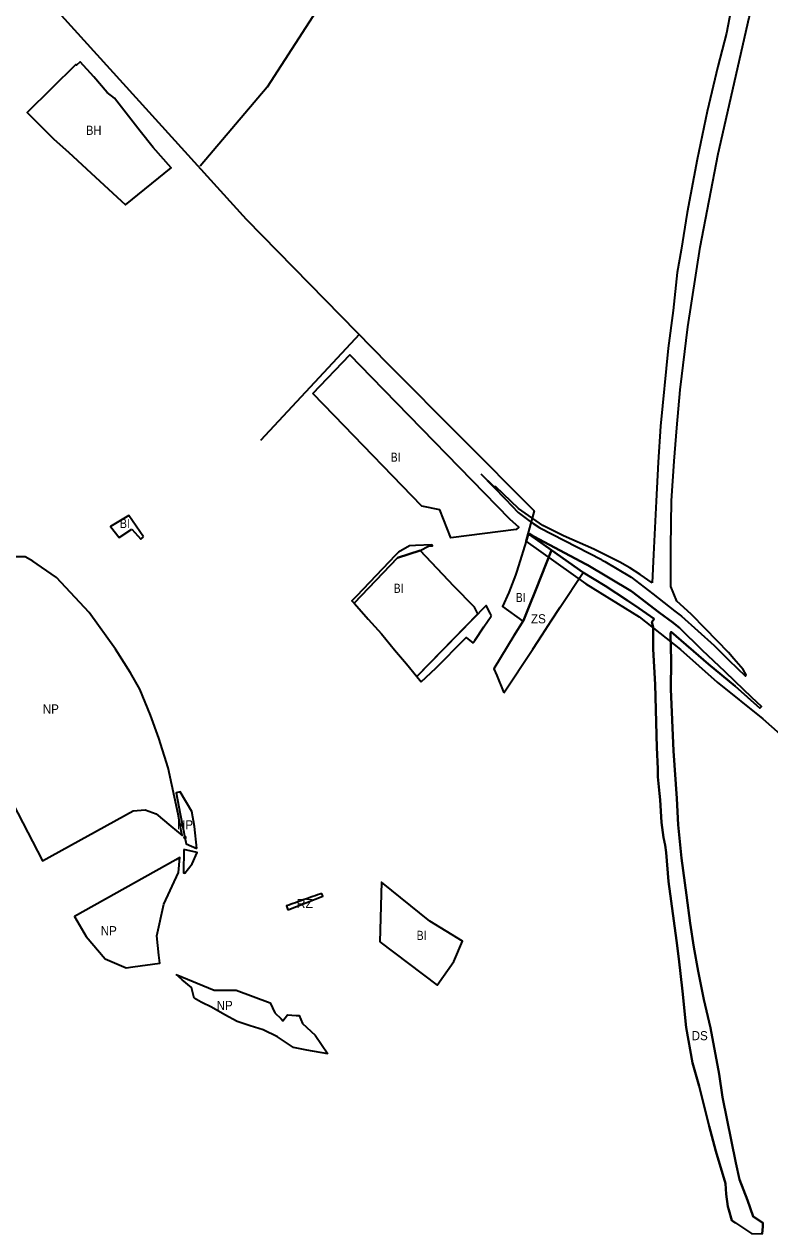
# Model space of a CAD drawing. Extents: x -650276 to -642489, y -1074311 to -1066658.
# Drawn here: x -646196 to -645218, y -1073293 to -1071706 of the extents above; entities that cross this region are included whole.
import ezdxf

# ---------------------------------------------------------------- set-up
doc = ezdxf.new("R2010")
doc.units = 0
doc.header["$LTSCALE"] = 4.8
doc.header["$PDMODE"] = 32
doc.header["$PDSIZE"] = 2.4
for name, color, linetype, lineweight in [('1', 7, 'Continuous', 35), ('15', 7, 'Continuous', 35), ('2', 7, 'Continuous', 35), ('24', 7, 'Continuous', 35), ('41', 7, 'Continuous', 35), ('48', 7, 'Continuous', 35), ('54', 7, 'Continuous', 35), ('6', 7, 'Continuous', 35)]:
    doc.layers.add(name, color=color, linetype=linetype, lineweight=lineweight)
doc.layers.add('62', color=7, linetype='Continuous')
doc.layers.add('63', color=7, linetype='Continuous')

msp = doc.modelspace()

# ---------------------------------------------------------------- linework, layer by layer
at = {"layer": '1'}
msp.add_lwpolyline([(-646102.04, -1071906.4), (-646068.317, -1071937.555), (-646062.91, -1071942.55), (-646002.93, -1071893.984), (-646026.64, -1071867.44), (-646043.49, -1071845.87), (-646077.32, -1071802.59), (-646087, -1071795), (-646104.5, -1071774.86), (-646122.16, -1071754.78), (-646127.12, -1071759.15), (-646127.84, -1071758.53), (-646191.57, -1071821.44), (-646174.69, -1071838.69), (-646156.59, -1071856.53), (-646137.74, -1071873.31)], close=True, dxfattribs=at)
at = {"layer": '15'}
for points in [[(-645763.06, -1072465.26), (-645706.039, -1072405.769), (-645676.53, -1072396.16)], [(-645661.3, -1072388.74), (-645682.59, -1072389.76), (-645690.37, -1072390.13), (-645705, -1072398.19), (-645708.94, -1072402.11)], [(-645676.53, -1072396.16), (-645676.53, -1072396.16), (-645665.32, -1072390.32), (-645660.16, -1072389.95), (-645661.3, -1072388.74)], [(-645708.94, -1072402.11), (-645760.02, -1072455.94), (-645765.95, -1072462.03), (-645763.06, -1072465.26)], [(-645582.84, -1072481.71), (-645584.46, -1072478.58), (-645589.862, -1072468.109), (-645680.87, -1072561.42), (-645675.13, -1072568.36)], [(-645607.07, -1072517.61), (-645605.95, -1072515.95), (-645604.82, -1072514.3), (-645592.9, -1072496.52), (-645583.13, -1072482.13), (-645582.84, -1072481.71)], [(-645675.13, -1072568.36), (-645655.65, -1072550.62), (-645617.87, -1072512.12), (-645615.95, -1072510.16), (-645607.07, -1072517.61)]]:
    msp.add_lwpolyline(points, dxfattribs=at)
at = {"layer": '2'}
msp.add_line((-645553.35, -1072508.1), (-645541.09, -1072487.98), dxfattribs=at)
for points in [[(-645817.219, -1072189.975), (-645768.649, -1072139.283), (-645740.45, -1072168.23), (-645559.34, -1072354.42), (-645546.82, -1072365.72), (-645550.41, -1072368.47), (-645636.37, -1072379.57), (-645650.78, -1072342.73), (-645674, -1072338), (-645789.298, -1072218.833)], [(-645729.36, -1072909.65), (-645654.16, -1072966.3), (-645632.23, -1072935.28), (-645620.92, -1072908.65), (-645663.52, -1072882.58), (-645726.9, -1072831.5)]]:
    msp.add_lwpolyline(points, close=True, dxfattribs=at)
for points in [[(-646039.16, -1072378.43), (-646058.64, -1072350.29), (-646082.55, -1072364.84), (-646071, -1072379.27), (-646054.43, -1072368.34)], [(-646054.43, -1072368.34), (-646042.65, -1072381.23), (-646039.16, -1072378.43)], [(-645541.09, -1072487.98), (-645533.15, -1072468.21), (-645524.87, -1072447.61), (-645503.98, -1072395.64), (-645532.75, -1072375.41), (-645535.05, -1072376.72), (-645549.6, -1072423.39), (-645551.54, -1072428.66), (-645559.92, -1072451.41), (-645568.38, -1072469.68), (-645541.56, -1072488.74)], [(-645632.1, -1072442.93), (-645676.53, -1072396.16), (-645706.039, -1072405.769), (-645763.06, -1072465.26), (-645753.128, -1072476.383), (-645744.38, -1072486.18), (-645726.95, -1072505.7), (-645709.92, -1072526.3), (-645694.51, -1072544.93), (-645680.87, -1072561.42), (-645600.883, -1072479.409)], [(-645632.1, -1072442.93), (-645638.82, -1072435.99), (-645676.53, -1072396.16), (-645706.039, -1072405.769), (-645763.06, -1072465.26), (-645753.128, -1072476.383)], [(-645600.945, -1072479.473), (-645605.17, -1072470.52), (-645632.1, -1072442.93)], [(-645753.128, -1072476.383), (-645744.38, -1072486.18), (-645726.95, -1072505.7), (-645709.92, -1072526.3)], [(-645709.92, -1072526.3), (-645694.51, -1072544.93), (-645680.87, -1072561.42), (-645600.945, -1072479.473)]]:
    msp.add_lwpolyline(points, dxfattribs=at)
at = {"layer": '24'}
msp.add_line((-645267.525, -1073275.443), (-645271.518, -1073261.16), dxfattribs=at)
for points in [[(-645339.904, -1072462.677), (-645347.551, -1072443.527), (-645347.677, -1072391.355), (-645346.62, -1072330.914), (-645343.458, -1072278.998), (-645339.908, -1072235.158), (-645335.367, -1072185.207), (-645325.498, -1072102.789), (-645309.01, -1071998.147), (-645285.617, -1071875.733), (-645244.798, -1071696.585), (-645235.793, -1071663.703), (-645230.436, -1071634.261), (-645227.905, -1071625.277), (-645222.48, -1071606.08)], [(-645339.904, -1072462.677), (-645347.551, -1072443.527), (-645347.677, -1072391.355), (-645346.62, -1072330.914), (-645343.458, -1072278.998), (-645339.908, -1072235.158), (-645335.367, -1072185.207), (-645325.498, -1072102.789), (-645309.01, -1071998.147), (-645285.617, -1071875.733), (-645244.798, -1071696.585), (-645235.793, -1071663.703), (-645230.436, -1071634.261), (-645227.905, -1071625.277), (-645222.48, -1071606.08)], [(-645255.662, -1071626.67), (-645261.094, -1071645.025), (-645264.841, -1071657.687), (-645269.077, -1071687.396), (-645274.868, -1071717.176), (-645286.175, -1071761.228), (-645300.076, -1071820.179), (-645313.153, -1071883.081), (-645326.343, -1071952.807)], [(-645255.662, -1071626.67), (-645261.094, -1071645.025), (-645264.841, -1071657.687), (-645269.077, -1071687.396), (-645274.868, -1071717.176), (-645286.175, -1071761.228), (-645300.076, -1071820.179), (-645313.153, -1071883.081)], [(-645313.153, -1071883.081), (-645326.343, -1071952.807), (-645334.118, -1072001.954), (-645339.455, -1072031.565), (-645344.819, -1072081.225), (-645351.358, -1072130.815), (-645361.317, -1072232.824), (-645364.435, -1072280.268), (-645366.951, -1072331.609), (-645370.624, -1072401.447), (-645372.228, -1072438.764)], [(-645326.343, -1071952.807), (-645334.118, -1072001.954), (-645339.455, -1072031.565), (-645344.819, -1072081.225), (-645351.358, -1072130.815), (-645361.317, -1072232.824), (-645364.435, -1072280.268), (-645366.951, -1072331.609), (-645370.624, -1072401.447), (-645372.228, -1072438.764)], [(-645372.228, -1072438.764), (-645387.894, -1072427.453), (-645401.441, -1072419.033), (-645414.631, -1072411.611), (-645448.831, -1072394.325), (-645488.64, -1072376.782), (-645515.437, -1072363.447), (-645547.593, -1072340.827), (-645577.33, -1072312.704), (-645579.217, -1072312.425), (-645596.405, -1072296.114)], [(-645596.405, -1072296.114), (-645564.4, -1072328.61), (-645547.72, -1072346.19), (-645532.07, -1072358.01), (-645531.65, -1072358.29), (-645528.27, -1072360.53), (-645519.57, -1072366.3), (-645438.64, -1072408.1)], [(-645372.228, -1072438.764), (-645387.894, -1072427.453), (-645401.441, -1072419.033), (-645414.631, -1072411.611), (-645448.831, -1072394.325), (-645488.64, -1072376.782), (-645515.437, -1072363.447), (-645547.593, -1072340.827), (-645577.33, -1072312.704), (-645579.217, -1072312.425), (-645596.405, -1072296.114)], [(-645596.405, -1072296.114), (-645564.4, -1072328.61), (-645547.72, -1072346.19), (-645532.07, -1072358.01), (-645531.65, -1072358.29), (-645528.27, -1072360.53), (-645519.57, -1072366.3), (-645438.64, -1072408.1)], [(-645462.646, -1072425.015), (-645503.98, -1072395.64), (-645532.75, -1072375.41), (-645534.3, -1072374.33), (-645533.08, -1072373.71)], [(-645533.08, -1072373.71), (-645534.3, -1072374.33), (-645532.75, -1072375.41), (-645503.98, -1072395.64), (-645462.65, -1072425.01)], [(-645533.08, -1072373.71), (-645527.33, -1072377.73), (-645459.31, -1072413.95), (-645456.52, -1072415.6), (-645400.12, -1072449.03), (-645396.94, -1072451.44), (-645370.226, -1072471.736)], [(-645456.52, -1072415.6), (-645459.31, -1072413.95), (-645527.33, -1072377.73), (-645533.08, -1072373.71)], [(-645438.64, -1072408.1), (-645437.6, -1072408.64), (-645434.19, -1072410.67), (-645399.77, -1072431.12), (-645371.356, -1072453.119), (-645342.284, -1072475.625)], [(-645438.64, -1072408.1), (-645437.6, -1072408.64), (-645434.19, -1072410.67), (-645399.77, -1072431.12), (-645371.356, -1072453.119), (-645342.284, -1072475.625), (-645333.62, -1072482.33), (-645290.76, -1072520.92)], [(-645369.364, -1072485.931), (-645389.731, -1072471.612), (-645404.64, -1072461.72), (-645433.91, -1072442.56), (-645462.646, -1072425.015)], [(-645462.646, -1072425.015), (-645433.91, -1072442.56), (-645404.64, -1072461.72), (-645389.731, -1072471.612), (-645369.364, -1072485.931)], [(-645396.94, -1072451.44), (-645400.12, -1072449.03), (-645456.52, -1072415.6)], [(-645345.079, -1072490.836), (-645362.81, -1072477.37), (-645370.226, -1072471.736), (-645396.94, -1072451.44)], [(-645370.226, -1072471.736), (-645362.81, -1072477.37), (-645345.079, -1072490.836)], [(-645342.284, -1072475.625), (-645333.62, -1072482.33), (-645290.76, -1072520.92)], [(-645290.76, -1072520.92), (-645271.74, -1072539.96), (-645249.9, -1072561.25), (-645248.967, -1072559.511), (-645252.768, -1072552.178), (-645265.009, -1072538.358), (-645272.276, -1072530.154), (-645302.303, -1072499.014), (-645320.805, -1072479.495), (-645339.904, -1072462.677)], [(-645290.76, -1072520.92), (-645271.74, -1072539.96), (-645249.9, -1072561.25), (-645248.967, -1072559.511), (-645252.768, -1072552.178), (-645265.009, -1072538.358), (-645272.276, -1072530.154), (-645302.303, -1072499.014), (-645320.805, -1072479.495), (-645339.904, -1072462.677)], [(-645364.524, -1072682.575), (-645366.022, -1072654.462), (-645368.173, -1072571.881), (-645370.755, -1072525.734), (-645370.928, -1072496.619), (-645372.72, -1072490.314), (-645369.364, -1072485.931)], [(-645369.364, -1072485.931), (-645372.72, -1072490.314), (-645370.928, -1072496.619), (-645370.755, -1072525.734)], [(-645345.079, -1072490.836), (-645336.33, -1072497.48), (-645306.46, -1072527.08), (-645276.93, -1072555.11), (-645263.7, -1072567.8), (-645242, -1072588.6), (-645241.87, -1072588.722), (-645228.96, -1072600.865), (-645230.845, -1072602.888)], [(-645242, -1072588.6), (-645263.7, -1072567.8), (-645276.93, -1072555.11), (-645306.46, -1072527.08), (-645336.33, -1072497.48), (-645345.079, -1072490.836)], [(-645347.292, -1072502.877), (-645348.253, -1072505.583), (-645347.214, -1072540.97), (-645347.795, -1072577.893), (-645344.152, -1072658.857), (-645339.96, -1072721.587), (-645338.023, -1072755.969), (-645333.718, -1072799.987)], [(-645338.023, -1072755.969), (-645339.96, -1072721.587), (-645344.152, -1072658.857), (-645347.795, -1072577.893), (-645347.214, -1072540.97), (-645348.253, -1072505.583), (-645347.292, -1072502.877), (-645298.498, -1072545.352)], [(-645230.845, -1072602.888), (-645263.217, -1072574.314), (-645298.498, -1072545.352), (-645347.292, -1072502.877)], [(-645370.755, -1072525.734), (-645368.173, -1072571.881), (-645366.022, -1072654.462), (-645364.524, -1072682.575), (-645364.786, -1072692.977), (-645362.708, -1072714.781)], [(-645298.498, -1072545.352), (-645263.217, -1072574.314), (-645230.845, -1072602.888), (-645228.96, -1072600.865), (-645241.87, -1072588.722), (-645242, -1072588.6)], [(-645357.272, -1072772.771), (-645359.76, -1072752.865), (-645361.874, -1072723.527), (-645362.708, -1072714.781), (-645364.786, -1072692.977), (-645364.524, -1072682.575)], [(-645362.708, -1072714.781), (-645361.874, -1072723.527), (-645359.76, -1072752.865), (-645357.272, -1072772.771), (-645355.121, -1072782.993)], [(-645317.65, -1072916.642), (-645322.284, -1072885.085), (-645327.091, -1072848.387), (-645333.718, -1072799.987), (-645338.023, -1072755.969)], [(-645271.518, -1073261.16), (-645272.747, -1073256.762), (-645275.269, -1073240.71), (-645276.125, -1073226.571), (-645288.647, -1073184.518), (-645297.395, -1073151.294), (-645310.558, -1073098.946), (-645319.052, -1073068.6), (-645327.554, -1073022.214), (-645332.517, -1072974.538), (-645337.34, -1072932.073), (-645340.345, -1072908.029), (-645350.822, -1072830.388), (-645354.019, -1072792.454), (-645355.121, -1072782.993), (-645357.272, -1072772.771)], [(-645355.121, -1072782.993), (-645354.019, -1072792.454), (-645350.822, -1072830.388), (-645340.345, -1072908.029), (-645337.34, -1072932.073), (-645332.517, -1072974.538), (-645327.554, -1073022.214), (-645319.052, -1073068.6), (-645310.558, -1073098.946), (-645297.395, -1073151.294), (-645288.647, -1073184.518), (-645276.125, -1073226.571), (-645275.269, -1073240.71), (-645272.747, -1073256.762), (-645271.518, -1073261.16), (-645267.525, -1073275.443), (-645263.03, -1073278.25), (-645241.72, -1073292.2), (-645227.744, -1073292.736), (-645227.199, -1073283.366), (-645226.847, -1073278.345), (-645239.9, -1073270.025), (-645247.051, -1073248.736), (-645257.842, -1073221.36)], [(-645333.718, -1072799.987), (-645327.091, -1072848.387), (-645322.284, -1072885.085), (-645317.65, -1072916.642)], [(-645317.65, -1072916.642), (-645311.772, -1072947.945), (-645304.24, -1072985.372), (-645295.788, -1073022.556)], [(-645304.24, -1072985.372), (-645311.772, -1072947.945), (-645317.65, -1072916.642)], [(-645257.842, -1073221.36), (-645262.388, -1073199.409), (-645279.878, -1073113.356), (-645284.269, -1073083.286), (-645295.788, -1073022.556), (-645304.24, -1072985.372)], [(-645295.788, -1073022.556), (-645284.269, -1073083.286), (-645279.878, -1073113.356), (-645262.388, -1073199.409), (-645257.842, -1073221.36), (-645247.051, -1073248.736), (-645239.9, -1073270.025), (-645226.847, -1073278.345), (-645227.199, -1073283.366), (-645227.744, -1073292.736)]]:
    msp.add_lwpolyline(points, dxfattribs=at)
at = {"layer": '41'}
msp.add_line((-645566.54, -1072582.88), (-645528.81, -1072525.54), dxfattribs=at)
msp.add_lwpolyline([(-645528.81, -1072525.54), (-645516.37, -1072506.64), (-645504.48, -1072488.58), (-645492.61, -1072470.54), (-645462.65, -1072425.01), (-645503.98, -1072395.64), (-645524.87, -1072447.61), (-645533.15, -1072468.21), (-645541.09, -1072487.98), (-645553.35, -1072508.1), (-645579.76, -1072551.45), (-645575.9, -1072560.13), (-645566.54, -1072582.88)], dxfattribs=at)
at = {"layer": '48'}
for points in [[(-646236.97, -1072678.31), (-646171.72, -1072803.51), (-646052.58, -1072737.82), (-646037.23, -1072736.38), (-646022.4, -1072741.58), (-646003.22, -1072757.85), (-645988.43, -1072769.93), (-645990.04, -1072761.78), (-645993.89, -1072742.23), (-646006.66, -1072681.4), (-646019.16, -1072642.35), (-646030.17, -1072612.31), (-646043.87, -1072578.12), (-646056.42, -1072556.49), (-646075.82, -1072525.54), (-646110.61, -1072477.49), (-646153.49, -1072431.54), (-646172.81, -1072418.2), (-646184.449, -1072410.256), (-646194.19, -1072404.62), (-646254.75, -1072404.25)], [(-645969.46, -1072787.03), (-645972.31, -1072758.48), (-645975.86, -1072738.61), (-645991.31, -1072712.86), (-645996.31, -1072714.11), (-645990.95, -1072741.65), (-645987.1, -1072761.2), (-645984.79, -1072772.91)], [(-645984.79, -1072772.91), (-645983.22, -1072780.88), (-645969.46, -1072787.03)], [(-645986.24, -1072788.33), (-645986.71, -1072819.26), (-645986.71, -1072819.26)], [(-645975.3, -1072807.37), (-645969.01, -1072792.28), (-645986.24, -1072788.33)], [(-645986.71, -1072819.26), (-645986.71, -1072819.26), (-645985.19, -1072819.72), (-645975.3, -1072807.37)], [(-645972.6, -1072983.41), (-645976.48, -1072969.55), (-645988.49, -1072959.28), (-645996.2, -1072952.69)], [(-645996.2, -1072952.69), (-645946.4, -1072973.05), (-645917.53, -1072972.93), (-645873.3, -1072989.79), (-645866.93, -1073002.72)], [(-645863.39, -1073034.25), (-645882.07, -1073025.22), (-645899.35, -1073019.65), (-645916.47, -1073014.03), (-645932.44, -1073005.5), (-645949.85, -1072995.57), (-645962.81, -1072989.45), (-645963.77, -1072989), (-645972.6, -1072983.41)], [(-645866.93, -1073002.72), (-645858.82, -1073010.74), (-645856.46, -1073013.07), (-645850.37, -1073005.42), (-645838.89, -1073006.18)], [(-645838.89, -1073006.18), (-645834.9, -1073006.45), (-645830.6, -1073016.92), (-645814.27, -1073032.11), (-645797.32, -1073056.62)], [(-645797.32, -1073056.62), (-645824.93, -1073051.83), (-645842.53, -1073048.19), (-645863.39, -1073034.25)]]:
    msp.add_lwpolyline(points, dxfattribs=at)
msp.add_lwpolyline([(-645993.47, -1072818.44), (-645991.37, -1072798.84), (-645996.8, -1072801.88), (-646129.91, -1072876.24), (-646114.5, -1072902.8), (-646089.39, -1072931.92), (-646062.04, -1072943.58), (-646053.287, -1072942.399), (-646017.65, -1072937.59), (-646019.21, -1072926.91), (-646021.64, -1072901.6), (-646012.37, -1072860.3)], close=True, dxfattribs=at)
msp.add_point((-645984.79, -1072772.91), dxfattribs=at)
at = {"layer": '54'}
msp.add_line((-645885.363, -1072251.506), (-645755.385, -1072111.972), dxfattribs=at)
for points in [[(-645648.577, -1071395.44), (-645803.784, -1071674.386), (-645877, -1071788), (-645965, -1071892)], [(-646336.784, -1071524.232), (-646218.737, -1071612.767), (-646164.374, -1071674.897), (-645904.456, -1071961.331), (-645718.199, -1072151.712), (-645526.944, -1072343.922), (-645538, -1072384), (-645459, -1072440), (-645389, -1072483), (-645335, -1072526), (-645287, -1072569), (-645227, -1072617), (-645139.573, -1072694.628), (-645084.365, -1072788.086)]]:
    msp.add_lwpolyline(points, dxfattribs=at)
at = {"layer": '6'}
for points in [[(-645834.208, -1072856.314), (-645837.027, -1072857.313), (-645839.908, -1072858.343), (-645842.74, -1072859.344), (-645845.619, -1072860.364), (-645848.628, -1072861.433), (-645851.48, -1072862.586), (-645850.187, -1072866.251), (-645850.17, -1072866.3), (-645849.705, -1072867.618), (-645849.703, -1072867.622)], [(-645849.703, -1072867.622), (-645848.52, -1072867.16), (-645803.84, -1072849.72), (-645805.159, -1072845.994)], [(-645805.159, -1072845.994), (-645808.177, -1072847.063), (-645811.148, -1072848.124), (-645813.978, -1072849.124), (-645816.948, -1072850.184), (-645819.779, -1072851.184), (-645822.726, -1072852.233), (-645825.527, -1072853.233), (-645828.409, -1072854.254), (-645834.208, -1072856.314)]]:
    msp.add_lwpolyline(points, dxfattribs=at)

# ---------------------------------------------------------------- texts
at = {"layer": '62'}
for s, width, p in [('BH', 0.9, (-646114.48, -1071850.818)), ('BI', 0.85, (-645715.06, -1072279.771)), ('BI', 0.85, (-645711.104, -1072451.727)), ('BI', 0.85, (-645551.06, -1072463.771)), ('ZS', 0.95, (-645531.06, -1072491.771)), ('NP', 0.95, (-646171.335, -1072610.048)), ('NP', 0.95, (-646095.335, -1072901.048)), ('BI', 0.85, (-645681, -1072907.167)), ('NP', 0.95, (-645943.335, -1072999.048)), ('DS', 0.95, (-645320.407, -1073038.717))]:
    msp.add_text(s, height=12, dxfattribs=dict(at, width=width)).set_placement(p)
msp.add_text('RZ', height=12, dxfattribs=at).set_placement((-645838.415, -1072865.224))
at = {"layer": '63'}
for s, width, p in [('BI', 0.85, (-646070.104, -1072366.727)), ('NP', 0.95, (-645995.335, -1072762.048))]:
    msp.add_text(s, height=12, dxfattribs=dict(at, width=width)).set_placement(p)

doc.saveas('drawing.dxf')
